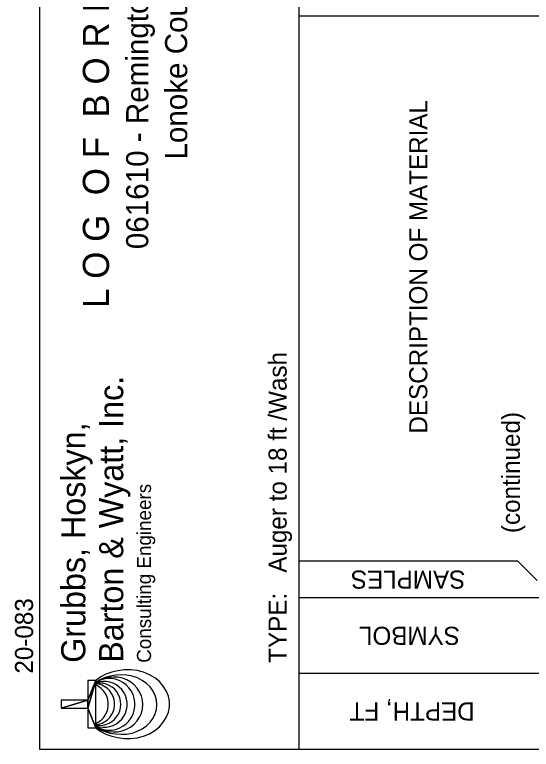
# Model space of a CAD drawing. Extents: x 1313964 to 1316843, y 2087046 to 2096619.
# Drawn here: x 1313974.69 to 1313989.21, y 2089873.43 to 2089894.09 of the extents above; entities that cross this region are included whole.
import ezdxf

# ---------------------------------------------------------------- set-up
doc = ezdxf.new("R2010")
doc.units = 0
doc.layers.add('B-Sub-Contour', color=7, linetype='Continuous')
doc.layers.add('Default', color=7, linetype='Continuous')

# ---------------------------------------------------------------- blocks, each defined once
blk = doc.blocks.new('DGRFC_GGHLOGO')
at = {"layer": 'Default'}
for points in [[(371581.68, 791230.32), (371581.68, 1050310.32), (295381.68, 1050310.32), (371581.68, 791230.32)], [(371581.68, 791230.32), (295381.68, 1050310.32), (295381.68, 791230.32), (371581.68, 791230.32)], [(295381.68, 791230.32), (104881.68, 791230.32), (104881.68, 715030.32), (295381.68, 791230.32)], [(295381.68, 791230.32), (104881.68, 715030.32), (562081.68, 715030.32), (295381.68, 791230.32)], [(295381.68, 791230.32), (562081.68, 715030.32), (371581.68, 791230.32), (295381.68, 791230.32)], [(562081.68, 715030.32), (562081.68, 791230.32), (371581.68, 791230.32), (562081.68, 715030.32)]]:
    blk.add_lwpolyline(points, close=True, dxfattribs=at)
for points in [[(105216.96, 715030.32), (100004.88, 709757.28), (68915.28, 666170.88), (42854.88, 615848.4), (22494.24, 560009.04), (8351.52, 500115.84), (792.48, 437662.32), (0, 374202.96), (7802.88, 311353.2), (23439.12, 250698), (46847.76, 193791.84), (77510.64, 142006.32), (114635.28, 96713.04), (157246.32, 59039.76), (204337.92, 29900.88), (254660.4, 10058.4), (306994.56, 0), (359968.8, 0), (412302.96, 10058.4), (462625.44, 29900.88), (509717.04, 59039.76), (552328.08, 96713.04), (589452.72, 142006.32), (620115.6, 193791.84), (643524.24, 250698), (659160.48, 311353.2), (666963.36, 374202.96), (666170.88, 437662.32), (658611.84, 500115.84), (644469.12, 560009.04), (624108.48, 615848.4), (598048.08, 666170.88), (566958.48, 709757.28), (561746.4, 715030.32)], [(111587.28, 715030.32), (108691.68, 711311.76), (85770.72, 670895.28), (67177.92, 625266.72), (53400.96, 575584.32), (44744.64, 523097.76), (41422.32, 469087.2), (42702.48, 414924.24), (52760.88, 362010.96), (69738.24, 311597.04), (93238.32, 264993.12), (122651.52, 223387.92), (157246.32, 187756.8), (196169.28, 159075.12), (238414.56, 137982.96), (282976.32, 125089.92), (328665.84, 120639.84), (374385.84, 124815.6), (419008.56, 137464.8), (461345.28, 158282.64), (500390.16, 186720.48), (535137.36, 222138.24), (564733.44, 263591.04), (588416.4, 310042.56), (605637.6, 360334.56), (615909.36, 413217.36), (618195.36, 467349.84), (615055.92, 521360.4), (606582.48, 573938.4), (592927.44, 623742.72), (574487.04, 669523.68), (551718.48, 710123.04), (547908.48, 715030.32)], [(113477.04, 715030.32), (111434.88, 712226.16), (91531.44, 674613.84), (76748.64, 633618.24), (67421.76, 590275.68), (63825.12, 545683.44), (65227.2, 500969.28), (74462.64, 457260.96), (90098.88, 415625.28), (111770.16, 377098.56), (138927.84, 342717.12), (170870.88, 313273.44), (206837.28, 289560), (245882.16, 272155.92), (287030.16, 261457.44), (329031.6, 257799.84), (371520.72, 261244.08), (412729.68, 271698.72), (451866, 288889.44), (487923.84, 312420), (520019.28, 341680.8), (547329.36, 375940.32), (569183.52, 414314.64), (585033.12, 455889.36), (594451.44, 499567.2), (596463.12, 544250.88), (593049.36, 588873.6), (583905.36, 632246.64), (569305.44, 673333.68), (549554.4, 711067.92), (546658.8, 715030.32)], [(117957.6, 715030.32), (116220.24, 712561.44), (98968.56, 677509.44), (87386.16, 640201.92), (81747.36, 601522.8), (82174.08, 562477.92), (88696.8, 523951.2), (101071.68, 486887.52), (119085.36, 452231.76), (142250.16, 420776.4), (170047.92, 393283.44), (201747.12, 370453.92), (236616.24, 352836.48), (273801.84, 340857.84), (312389.52, 334792.32), (351464.88, 334792.32), (390052.56, 340857.84), (427238.16, 352836.48), (462107.28, 370453.92), (493806.48, 393283.44), (521573.76, 420776.4), (544769.04, 452231.76), (562752.24, 486887.52), (575157.6, 523951.2), (581649.84, 562477.92), (582076.56, 601522.8), (576437.76, 640201.92), (564855.36, 677509.44), (547634.16, 712561.44), (545896.8, 715030.32)], [(124632.72, 715030.32), (123809.76, 713353.92), (113934.24, 680252.64), (109301.28, 646023.6), (110002.32, 611459.28), (116006.88, 577443.6), (127223.52, 544769.04), (143316.96, 514228.08), (163982.4, 486521.76), (188640.72, 462351.12), (216743.28, 442264.8), (247619.52, 426780.96), (280507.44, 416234.88), (314645.04, 410900.88), (349209.36, 410900.88), (383316.48, 416234.88), (416234.88, 426780.96), (447080.64, 442264.8), (475213.68, 462351.12), (499872, 486521.76), (520506.96, 514228.08), (536630.88, 544769.04), (547847.52, 577443.6), (553852.08, 611459.28), (554553.12, 646023.6), (549920.16, 680252.64), (540014.16, 713353.92), (539221.68, 715030.32)], [(130972.56, 715030.32), (130454.4, 713079.6), (127284.48, 680740.32), (129235.2, 648309.6), (136306.56, 616579.92), (148254.72, 586343.76), (164805.36, 558393.6), (185562.24, 533400), (210007.2, 511972.56), (237530.64, 494659.92), (267401.04, 481919.28), (298917.36, 474024.96), (331317.6, 471190.32), (363717.84, 473506.8), (395356.08, 480882.96), (425470.32, 493166.4), (453237.6, 510021.84), (478017.84, 531053.04), (499170.96, 555711.36), (516178.8, 583417.68), (528614.64, 613440.48), (536173.68, 645048.24), (538642.56, 677448.48), (535990.8, 709818.24), (534710.64, 715030.32)], [(135483.6, 715030.32), (135483.6, 714420.72), (140482.32, 683727.36), (150174.96, 654192.24), (164378.64, 626546.88), (182727.6, 601431.36), (204764.64, 579485.76), (229941.12, 561258.72), (257647.44, 547176.96), (287243.52, 537606.24), (317936.88, 532759.92), (349026.48, 532759.92), (379719.84, 537606.24), (409315.92, 547176.96), (437022.24, 561258.72), (462198.72, 579485.76), (484235.76, 601431.36), (502584.72, 626546.88), (516788.4, 654192.24), (526481.04, 683727.36), (531479.76, 714420.72), (531479.76, 715030.32)], [(146151.6, 715030.32), (160690.56, 687811.68), (179679.6, 662574.24), (202326.24, 640567.68), (228112.32, 622279.68), (256367.28, 608167.44), (286481.52, 598566.24), (317693.04, 593719.92), (349270.32, 593719.92), (380481.84, 598566.24), (410596.08, 608167.44), (438851.04, 622279.68), (464637.12, 640567.68), (487283.76, 662574.24), (506272.8, 687811.68), (520811.76, 715030.32)]]:
    blk.add_lwpolyline(points, dxfattribs=at)

msp = doc.modelspace()

# ---------------------------------------------------------------- linework, layer by layer
at = {"layer": 'B-Sub-Contour'}
for points in [[(1314036.804, 2089873.434), (1314036.804, 2089916.306), (1313975.385, 2089916.306), (1313975.385, 2089873.434), (1314036.804, 2089873.434)], [(1313982.683, 2089873.434), (1313982.683, 2089916.306)], [(1314034.372, 2089894.049), (1313982.683, 2089894.049)], [(1313988.824, 2089878.725), (1313982.683, 2089878.725)], [(1313989.372, 2089878.178), (1313988.824, 2089878.725)], [(1314034.372, 2089877.691), (1313982.683, 2089877.691)], [(1314034.372, 2089875.563), (1313982.683, 2089875.563)]]:
    msp.add_lwpolyline(points, dxfattribs=at)

# ---------------------------------------------------------------- block references
at = {"layer": 'B-Sub-Contour', "xscale": 2.894891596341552e-06, "yscale": 2.894891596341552e-06, "rotation": 90}
msp.add_blockref('DGRFC_GGHLOGO', (1313979.034, 2089873.738), dxfattribs=at)

# ---------------------------------------------------------------- texts
at = {"layer": 'B-Sub-Contour'}
for s, height, rotation, p in [('L O G  O F  B O R I N G  N O.  S1', 0.7352, 90, (1313977.337, 2089885.845)), ('061610 - Remington Road over I-40', 0.62209, 90, (1313978.44, 2089887.499)), ('Lonoke County, Arkansas', 0.62209, 90, (1313979.534, 2089890.018)), ('DESCRIPTION OF MATERIAL', 0.50899, 90, (1313986.282, 2089882.313)), ('TYPE:   Auger to 18 ft /Wash', 0.50899, 90, (1313982.329, 2089875.867)), ('Barton & Wyatt, Inc.', 0.67865, 90, (1313977.736, 2089875.867)), ('(continued)', 0.50899, 90, (1313988.885, 2089879.515)), ('Grubbs, Hoskyn,', 0.67865, 90, (1313976.672, 2089875.867)), ('Consulting Engineers', 0.39588, 90, (1313978.518, 2089875.867)), ('SAMPLES', 0.509, 180, (1313987.35, 2089878.462)), ('20-083', 0.509, 90, (1313975.203, 2089875.563)), ('SYMBOL', 0.509, 180, (1313987.199, 2089876.881)), ('DEPTH, FT', 0.509, 180, (1313987.615, 2089874.753))]:
    msp.add_text(s, height=height, rotation=rotation, dxfattribs=at).set_placement(p)

doc.saveas('drawing.dxf')
